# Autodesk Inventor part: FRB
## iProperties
Manager: Klinkenberg
Author: Wj
Shininess: 60.0
Length Units: 11269
Angle Units: 11283
Time Units: 11279
Mass Units: 11290
Length Display Precision: 3
Angle Display Precision: 2
Compacted: True
PropertySet Name: _Private Model Information
Created: 2001-11
Part Number: FRB
Material: Nylon, Black
Description: FRB 5/140
Document SubType Name: Sheet Metal
Designer: Wj
Control State: 0
Master: False
Checked Out: False
PropertySet Name: Design Tracking Control
Density: 7.859999999999999
Volumn: 9.928283260114041
Area: 31.0262794534655
PropertySet Name: Model Information
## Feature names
1. Plate2
2. Bend1
